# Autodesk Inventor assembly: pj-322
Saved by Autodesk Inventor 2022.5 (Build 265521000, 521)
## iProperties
Created: 2024-12
Part Number: pj-322
Document SubType Name: Assembly
Designer: AdminForWorker
Title: pj-322 v1
Author: AdminForWorker
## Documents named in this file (6)
- c:\worker\convert-fusion-r05-cosv3\tmp\job-1\35\temp\files\545dca92-a972-481a-9197-dd1a1176500e\pj-322 v1.iam
- c:\worker\convert-fusion-r05-cosv3\tmp\job-1\35\temp\files\545dca92-a972-481a-9197-dd1a1176500e\tip_lead.ipt
- c:\worker\convert-fusion-r05-cosv3\tmp\job-1\35\temp\files\545dca92-a972-481a-9197-dd1a1176500e\Component2_1.ipt
- c:\worker\convert-fusion-r05-cosv3\tmp\job-1\35\temp\files\545dca92-a972-481a-9197-dd1a1176500e\Component3_1.ipt
- c:\worker\convert-fusion-r05-cosv3\tmp\job-1\35\temp\files\545dca92-a972-481a-9197-dd1a1176500e\Component4_1.ipt
- c:\worker\convert-fusion-r05-cosv3\tmp\job-1\35\temp\files\545dca92-a972-481a-9197-dd1a1176500e\Part112.ipt
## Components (5 placed, 5 different names)
1. tip_lead:1
2. Component2:1
3. Component3:1
4. Component4:1
5. Part112
